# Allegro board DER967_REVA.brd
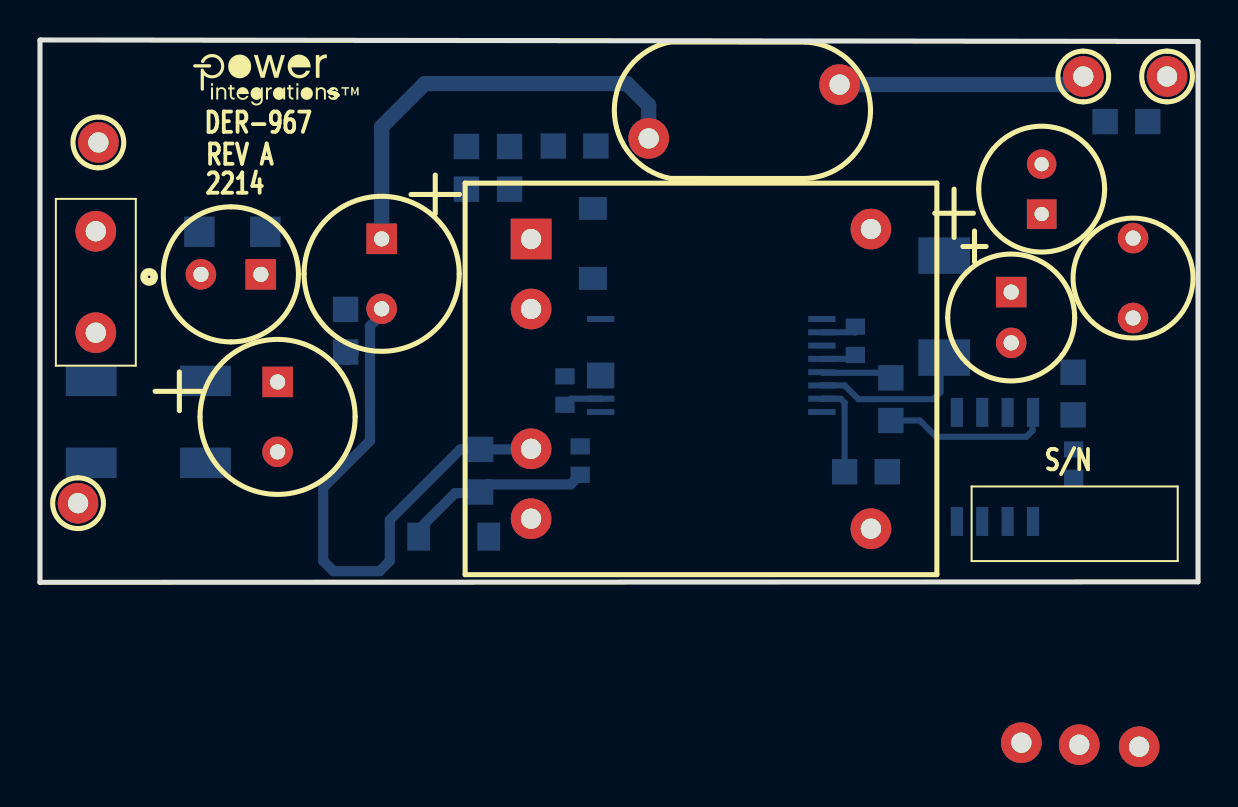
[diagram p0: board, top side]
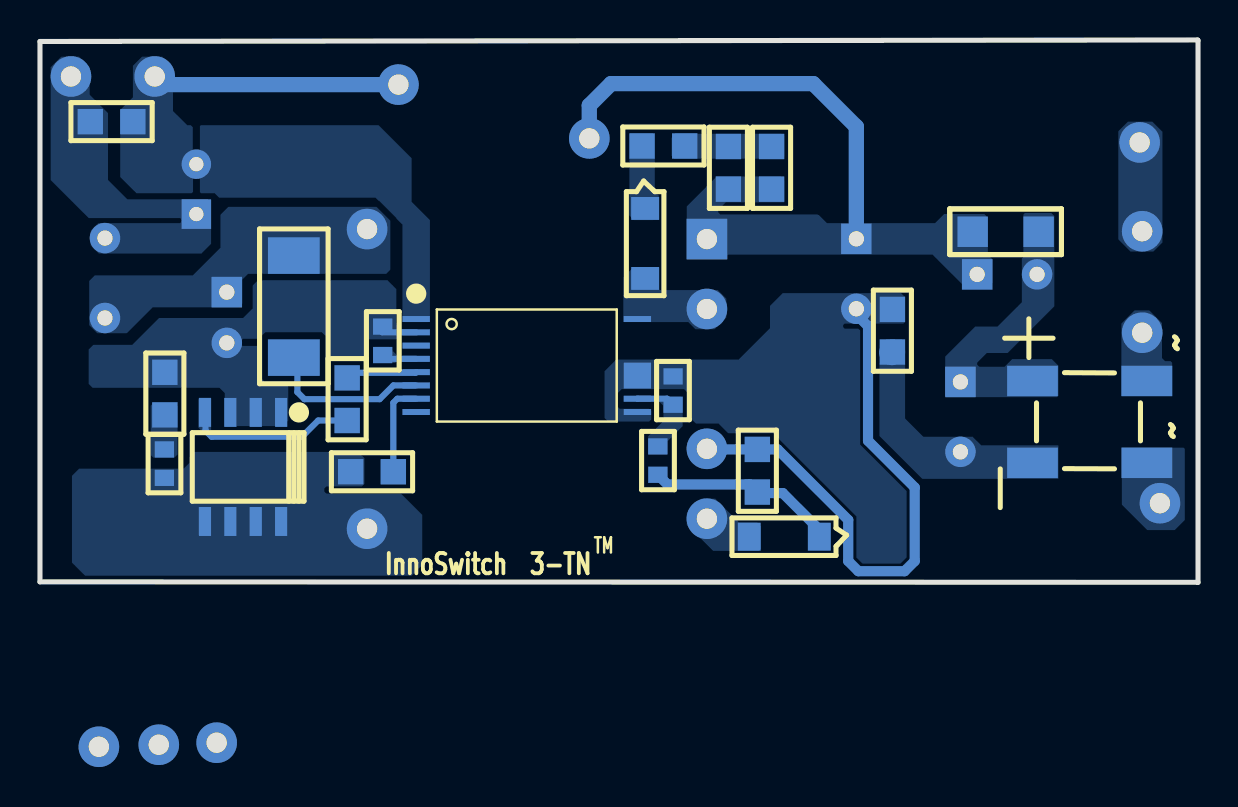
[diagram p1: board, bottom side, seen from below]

Outline 57.94 x 27.15 mm; copper layers: TOP, BOTTOM. Coordinates in mm from the lower left corner of the outline.
Outline path: 0,27.13 0,0 57.94,0.03 57.94,27.08 0.03,27.15 0,27.13

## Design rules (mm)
constraint set DEFAULT: min track width 0.508
net group B+: nets GND N2618450 N2618858

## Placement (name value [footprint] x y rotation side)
BR1  ABS210-13  [PISMD_SOPA-4]  8.28 10.08 90 bottom
C1  5.6 uF  [PIPOLCAPCYLD315LS138D030]  11.89 10.03 270 top
C2  5.6 uF  [PIPOLCAPCYLD315LS138D030]  17.09 17.2 270 top
C3  100 pF  [PISMC0805]  23.5 21.82 270 bottom
C4  22 uF  [PISMC0805]  22.05 4.52 90 bottom
C5  0.47 uF  [PISMC0603]  26.26 10.31 270 bottom
C6  1000 pF  [PISMC0603]  51.71 5.23 90 bottom
C7  2.2 uF  [PISMC0603]  40.79 11.38 90 bottom
C8  560 uF  [PIPOLCAPCYLD250LS100030]  48.59 14.53 270 top
C9  1 uF  [PISMC0805]  55.42 23.06 180 bottom
C10  470 pF  [PINPCAPRAD374X275LS394D040]  30.12 23.62 0 top
C11  100 uF  [PIPOLCAPCLYD248LS098028]  50.11 19.68 90 top
D1  S1MLHRVG  [PI_SM_SOD-123_12]  27.66 18.72 270 bottom
D2  SM4003PL-TP  [PI_SM_SOD-123_12]  18.95 2.29 0 bottom
F1  2 A  [PI_RST_MICROFUSE]  2.79 12.5 90 top
GND  GND  [PITPKEYSTONE100X100]  52.2 25.32 0 top
L  WHT  [PITPKEYSTONE100X100]  2.92 22.02 0 top
L1  330 uH  [PI_CHOKE_RL5480-2_D2]  11.05 15.42 180 top
L2  4.7 uH  [PISMR0805]  15.29 11.53 90 bottom
L3  1.7 uH  [PICHOKE6MM2PIN4MMLSD030]  54.69 13.23 0 top
N  BLK  [PITPKEYSTONE100X100]  1.91 3.96 0 top
NOREF  -  []  -151.06 50.22 0 top
NOREF#2  -  []  0.03 0 90 top
NOREF#3  -  []  -228.88 -148.79 0 top
NOREF#4  -  []  7.11 26.34 0 top
NOREF#5  -  []  0.05 27.18 0 top
Q1  AO4264E  [PISMSO8]  45.87 8.51 0 bottom
R1  10 k  [PISMR1206]  7.98 17.55 0 bottom
R2  240 k  [PISMR0805]  21.34 21.82 270 bottom
R3  22  [PISMR0805]  27.81 21.84 180 bottom
R4  7.5 k  [PISMR0603]  27.03 5.38 90 bottom
R6  47  [PISMR0805]  42.39 5.54 180 bottom
R7  10  [PISMR0805]  51.69 10.52 270 bottom
R8  0.0  [PISMR2010]  45.24 16.36 270 bottom
R9  0.0  [PISMR0805]  42.57 8.1 90 bottom
T1  EF16  [PI_BOBBIN_EF16_9P_5X4_LNK574A]  33.07 10.19 270 top
U1  INN3072M  [PI_SM_MINSOP16A_1]  39.12 13.18 270 bottom
V+  RED  [PITPKEYSTONE100X100]  56.39 25.32 0 top

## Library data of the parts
BR1 = DIODE BRIDGE_+~~-: alternate symbols: (pismd_SOPA-4a,pi_sm_soic4_slot)
C1 C2 = CAP POL: alternate symbols: (pipolcapcyld315ls138d030h)
C3-C6 C9 C10 = CAP NP
C7 = CAP NP: alternate symbols: (pismc0603_1)
C8 = CAP POL
C11 = CAP POL: alternate symbols: (pipolcapclyd6p3x9mm_h)
D1 D2 = DIODE
F1 = FUSE: alternate symbols: (pirstmicrofusehoz)
GND L N V+ = TESTPOINT
L1 = INDUCTOR_dot2: alternate symbols: (pi_choke_RL5480-2H_d2)
L2 L3 = INDUCTOR
Q1 = FET_P_SGD_123_4_5678
R1-R4 R6-R8 = R
R9 = R: alternate symbols: (pismr0805_1)
T1 = BEF16_H_9P_5x4
U1 = Inno3TNMinSOP16_5

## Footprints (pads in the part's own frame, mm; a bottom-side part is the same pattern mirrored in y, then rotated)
PI_BOBBIN_EF16_9P_5X4_LNK574A
  rect 2.032x2.032 hole 1.016: 1(-7,-8.5)
  round 2.032 hole 1.016: 2(-3.5,-8.5) 3(18.212,16.027) 4(3.5,-8.5) 5(7,-8.5) 6(7.5,8.5) 7(18.415,21.92) 8(18.313,18.923) 9(-7.5,8.5)
PI_CHOKE_RL5480-2_D2
  rect 1.524x1.524 hole 0.762: 1(0,0)
  round 1.524 hole 0.762: 2(2.997,0)
PI_RST_MICROFUSE
  round 2.032 hole 1.016: 1(0,0) 2(5.08,0)
PI_SM_MINSOP16A_1
  rect 0.3x1.369 smd: 1(0,0) 2(0.666,0) 3(1.331,0) 4(1.994,0) 5(2.659,0) 6(3.325,0) 7(3.99,0) 8(4.656,0) 9(4.656,11.067) 10(3.99,11.067) 16(0,11.067)
  rect 1.293x1.369 smd: 11(2.83,11.067)
PI_SM_SOD-123_12
  rect 1.143x1.397 smd: 1(0,0) 2(3.505,0)
PICHOKE6MM2PIN4MMLSD030
  round 1.524 hole 0.762: 1(0,0) 2(0,4)
PINPCAPRAD374X275LS394D040
  round 2.032 hole 1.016: 1(0.33,-1.397) 2(9.881,1.295)
PIPOLCAPCLYD248LS098028
  rect 1.473x1.473 hole 0.711: 1(-1.25,0)
  round 1.473 hole 0.711: 2(1.25,0)
PIPOLCAPCYLD250LS100030
  rect 1.524x1.524 hole 0.762: 1(0,0)
  round 1.524 hole 0.762: 2(2.54,0)
PIPOLCAPCYLD315LS138D030
  rect 1.524x1.524 hole 0.762: 1(0,0)
  round 1.524 hole 0.762: 2(3.5,0)
PISMC0603
  rect 0.813x0.965 smd: 1(0,0) 2(1.422,0)
PISMC0805
  rect 1.27x1.27 smd: 1(0,0) 2(2.134,0)
PISMD_SOPA-4
  rect 1.524x2.54 smd: 1(0,0) 2(0,-5.72) 3(-4.1,-5.72) 4(-4.1,0)
PISMR0603
  rect 0.813x0.965 smd: 1(0,0) 2(1.422,0)
PISMR0805
  rect 1.27x1.27 smd: 1(0,0) 2(2.134,0)
PISMR1206
  rect 1.524x1.524 smd: 1(0,0) 2(3.302,0)
PISMR2010
  rect 1.829x2.591 smd: 1(0,0) 2(5.105,0)
PISMSO8
  rect 0.61x1.448 smd: 1(0,0) 2(1.27,0) 3(2.54,0) 4(3.81,0) 5(3.81,5.461) 6(2.54,5.461) 7(1.27,5.461) 8(0,5.461)
PITPKEYSTONE100X100
  round 2.032 hole 1.016: 1(0,0)

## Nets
GND: C9.2 C10.2 C11.2 GND.1 U1.1
0: C2.2 C4.2 C5.1 L2.2 T1.4 U1.9 U1.11
B+: C2.1 C3.2 C10.1 L1.1 R1.2 R2.2 T1.1
V+: C9.1 C11.1 L3.2 V+.1
N2618450: C8.1 L3.1 R8.1 T1.9
N2618494: BR1.1 C1.1 L1.2 R1.1
N2618826: C3.1 R2.1 R3.2
N2618846: C6.1 Q1.5 Q1.6 Q1.7 Q1.8 R6.1 T1.6
N2618854: C6.2 R7.2
N2618858: C7.2 C8.2 Q1.1 Q1.2 Q1.3(S3) R7.1 U1.2
N2618940: BR1.4 C1.2 L2.1
N2618994: D1.1 R3.1
N2618998: D1.2 T1.2 U1.16
N2619084: C4.1 D2.1 R4.1
N2619088: Q1.4 R9.1
N2619426: C5.2 R4.2 U1.10
N2626861: BR1.3 N.1
N11196837: R8.2 U1.6
N11197056: R6.2 U1.7
N11221476: D2.2 T1.5
N11228330: F1.2 L.1
N11228899: BR1.2 F1.1
N11236373: C7.1 U1.4
N11252892: R9.2 U1.5

Pads without a net: T1 3 7 8; U1 3 8

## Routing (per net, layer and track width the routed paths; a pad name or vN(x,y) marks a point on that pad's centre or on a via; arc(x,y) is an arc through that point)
GND: length 12.4
  BOTTOM w0.762: C10.2 51.79,24.92 GND.1
0: length 28.2
  BOTTOM w0.508: T1.4 24.54,6.65 C4.2 21.03,6.65 17.5,3.12 17.5,1.07 16.99,0.56 14.68,0.56 14.17,1.07 14.17,4.75 16.51,7.09 16.51,12.83 17.09,13.41 C2.2
B+: length 22
  BOTTOM w0.762: C2.1 17.09,22.81 19.25,24.97 29.36,24.97 30.45,23.88 C10.1
N2618858: length 2
  BOTTOM w0.305: C7.2 40.81,12.78 40.81,12.52 U1.2
N2618940: length 0
  BOTTOM w1.27: L2.1 15.32,11.51
N2619084: length 9.6
  BOTTOM w0.508: R4.1 26.54,4.9 22.43,4.9 C4.1 22,4.47 20.78,4.47 18.95,2.64 D2.1
N2619088: length 8.5
  BOTTOM w0.305: Q1.4 49.66,8.48 49.66,7.59 49.35,7.29 44.83,7.29 44.02,8.1 R9.1
N2619426: length 1.9
  BOTTOM w0.305: U1.10 28.05,9.19 26.57,9.19 C5.2
N11196837: length 8.2
  BOTTOM w0.305: U1.6 40.26,9.86 40.94,9.17 44.7,9.17 45.06,9.53 45.06,11.07 R8.2
N11197056: length 4.7
  BOTTOM w0.305: R6.2 40.26,8.99 40.06,9.19 U1.7
N11236373: length 1.8
  BOTTOM w0.305: U1.4 40.91,11.19
N11252892: length 3.6
  BOTTOM w0.305: U1.5 39.15,10.49 42.32,10.49 R9.2

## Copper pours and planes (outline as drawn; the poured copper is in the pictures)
GND on BOTTOM: 49.89,22.89 49.94,22.83 49.94,21.34 50.01,21.26 50.24,21.26 50.29,21.31 50.29,22.78 50.39,22.89 50.57,22.89 51.28,23.6 51.28,25.78 51.82,26.31 52.83,26.31 53.29,25.86 53.29,24.28 53.91,23.66 53.91,23.63 53.92,23.62 53.92,20.29 53.11,19.48 50.34,19.48 50.28,19.55 50.28,20.56 50.22,20.62 50.01,20.62 49.94,20.55 49.94,19.53 49.89,19.48 49.2,19.48 48.97,19.25 41.15,19.25 39.8,17.91 39.8,13.18 39.65,13.03 38.53,13.03 38.43,13.13 38.43,18.14 39.34,19.05 39.34,21.23 41,22.89
0 on BOTTOM: 14.86,14.48 14.66,14.27 14.66,13.03 14.73,12.95 17.68,12.95 17.75,12.88 17.75,12.78 17.68,12.7 16.99,12.7 16.9,12.61 16.9,6.88 16.89,6.88 14.58,4.57 14.58,1.24 14.88,0.94 16.79,0.94 17.09,1.24 17.09,3.3 21.26,7.47 23.51,7.47 23.99,7.95 25.12,7.95 25.45,8.28 25.45,9.41 25.72,9.68 28.83,9.68 29.06,9.45 29.06,8.81 28.93,8.69 27.46,8.69 27.36,8.59 27.36,8.15 27.46,8.05 29.51,8.05 29.69,8.23 29.69,10.57 29.11,11.15 22.99,11.15 21.41,12.73 21.41,13.84 20.78,14.48
B+ on BOTTOM: 10.29,14.99 10.62,14.66 11.53,14.66 13.28,16.41 23.5,16.41 23.7,16.21 23.7,16.18 25.4,16.18 25.58,16.36 25.58,18.82 24.08,20.32 20.9,20.32 20.7,20.12 20.7,19.02 23.62,19.02 24,18.64 24,18.52 23.9,18.41 19.02,18.41 19,18.39 18.97,18.39 18.57,17.98 13.16,17.98 12.7,18.44 10.69,18.44 10.5,18.25 10.52,18.24 10.52,16.41 10.29,16.18
V+ on BOTTOM: 55.98,26.31 56.87,26.31 57.4,25.78 57.4,20.14 55.5,18.24 50.93,18.24 50.85,18.16 50.85,18.06 50.93,17.98 55.02,17.98 55.4,17.6 55.4,16.87 54.99,16.46 49.86,16.46 49.38,16.94 49.38,19.02 49.53,19.18 53.57,19.18 54.53,20.14 54.53,23.5 55.45,24.41 55.45,25.78
N2618450 on BOTTOM: 53.59,12.47 55.07,12.47 55.47,12.88 55.47,15.09 55.19,15.37 50.29,15.37 48.91,16.75 48.91,18.4 48.51,18.8 41.1,18.8 40.41,18.11 40.41,15.65 40.61,15.44 47.52,15.44 47.82,15.15 47.82,13.96 48.01,13.77 52.3,13.77
N2618494 on BOTTOM: 7.34,18.49 8.66,18.49 8.74,18.41 8.74,16.28 8.81,16.21 8.81,14.02 10.03,12.8 11.15,12.8 12.65,11.3 12.65,9.37 12.55,9.27 7.06,9.27 6.97,9.36 6.99,9.37 6.99,10.85 7.32,11.18 9.3,11.18 9.68,10.79 10.95,10.79 11.05,10.9 11.05,11 10.57,11.48 9.52,11.48 7.19,13.82 7.19,18.34
N2618826 on BOTTOM: 20.7,21.34 20.7,22.33 20.83,22.45 26.14,22.45 26.34,22.25 26.34,21.36 26.19,21.21 20.83,21.21
N2618846 on BOTTOM: 39.34,0.33 38.81,0.86 38.81,3.38 39.88,4.44 43.61,4.44 43.71,4.55 43.71,4.7 43.61,4.8 41.83,4.8 41.71,4.93 41.71,6.22 42.01,6.53 50.22,6.53 50.46,6.29 50.46,5.98 50.75,5.69 55.98,5.69 56.34,5.33 56.34,0.99 55.68,0.33
N2618854 on BOTTOM: 51.21,8.97 52.27,8.97 52.4,8.84 52.4,6.38 52.27,6.25 51.21,6.25 51.05,6.4 51.05,8.81
N2618858 on BOTTOM: 40.55,15.13 47.03,15.13 47.29,14.86 47.29,13.72 47.78,13.23 51.98,13.23 53.33,11.89 55.27,11.89 55.5,11.66 55.5,9.93 55.31,9.74 48.96,9.74 48.69,9.47 48.69,7.82 45.8,7.82 45.52,8.1 45.52,9.86 45.69,10.03 46.69,10.03 46.84,10.19 46.84,11.84 47.8,11.84 47.88,11.91 47.88,12.09 47.78,12.19 46.86,12.19 46.84,12.22 46.84,12.34 46.66,12.52 43.84,12.52 43.64,12.32 43.64,11.28 43.56,11.2 41.63,11.2 41.59,11.24 41.59,12.05 41.48,12.17 40.08,12.17 39.88,12.37 39.8,12.37 39.8,12.65 40.11,12.95 40.11,14.68
N2618940 on BOTTOM: 6.99,6.86 10.85,6.86 11.28,7.29 13.74,7.29 14.66,8.2 14.66,11.99 14.83,12.17 15.6,12.17 15.93,11.84 15.93,10.97 15.94,10.96 15.94,7.33 13.79,5.18 6.99,5.18
N2618994 on BOTTOM: 27.18,22.33 27.33,22.48 28.37,22.48 28.45,22.4 28.45,18.36 28.22,18.14 27.25,18.14 26.97,18.41 26.97,19.35 27.18,19.56
N2618998 on BOTTOM: 24.03,14.63 26.92,14.63 26.97,14.68 26.97,15.67 27.08,15.77 28.24,15.77 28.75,15.27 28.75,13.06 28.73,13.03 25.5,13.03 25.15,12.67 24.18,12.67 23.6,13.26 23.6,14.2
N2619088 on BOTTOM: 49.38,9.17 49.38,7.52 49.48,7.42 49.68,7.42 50.01,7.75 50.01,9.17
N2619426 on BOTTOM: 25.78,7.82 25.78,9.17 25.91,9.3 26.97,9.3 26.97,9.07 26.75,8.84 26.75,8.08 27.51,7.32 27.51,6.4 26.59,6.4 26.54,6.45 26.54,7.06
N2626861 on BOTTOM: 0.66,3.12 0.66,6.68 0.72,6.74 3.8,6.74 3.81,6.73 3.81,3.89 2.54,2.62 1.17,2.62
N11221476 on BOTTOM: 21.87,1.68 21.87,2.82 22.05,3 22.96,3 24.16,4.19 24.84,4.19 25.58,3.45 25.58,2.87 24.89,2.18 24.87,2.18 24.26,1.57 21.97,1.57
N11228330 on BOTTOM: 1.78,17.02 1.78,22.56 2.29,23.06 3.51,23.06 3.99,22.58 3.99,17.17 3.38,16.56 2.24,16.56
N11228899 on BOTTOM: 1.3,9.32 3.81,9.32 3.84,9.35 3.84,12.95 3.17,13.61 2.44,13.61 1.8,12.98 1.8,11.23 1.65,11.07 1.37,11.07 1.3,11

Small or netless copper shapes (teardrops, artwork), in the pictures only: 1 on BOTTOM

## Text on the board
Ref Des/Silkscreen Bottom: TM | InnoSwitch  3-TN
Ref Des/Silkscreen Top: DER-967 | 2214 | REV A | S/N
User.5: 14.  FAB HOUSE LOGO,DATE CODE TO BE IN SILK SCREEN ONLY.DO NOT USE COPPER. | 13.  MATERIAL FR4 COPPER 2oz THICKNESS 0.062" | DELETE THESE PIN
User.8: FIGURE | FINISHED_SIZE | 28.0 | 30.0 | 40.0 | DRILL CHART: TOP to BOTTOM | ALL UNITS ARE IN MILS | TOLERANCE_DRILL | +0.0/-0.0 | +3.0/-3.0 | PLATED | QTY | 2 | 1 | 9 | 14
